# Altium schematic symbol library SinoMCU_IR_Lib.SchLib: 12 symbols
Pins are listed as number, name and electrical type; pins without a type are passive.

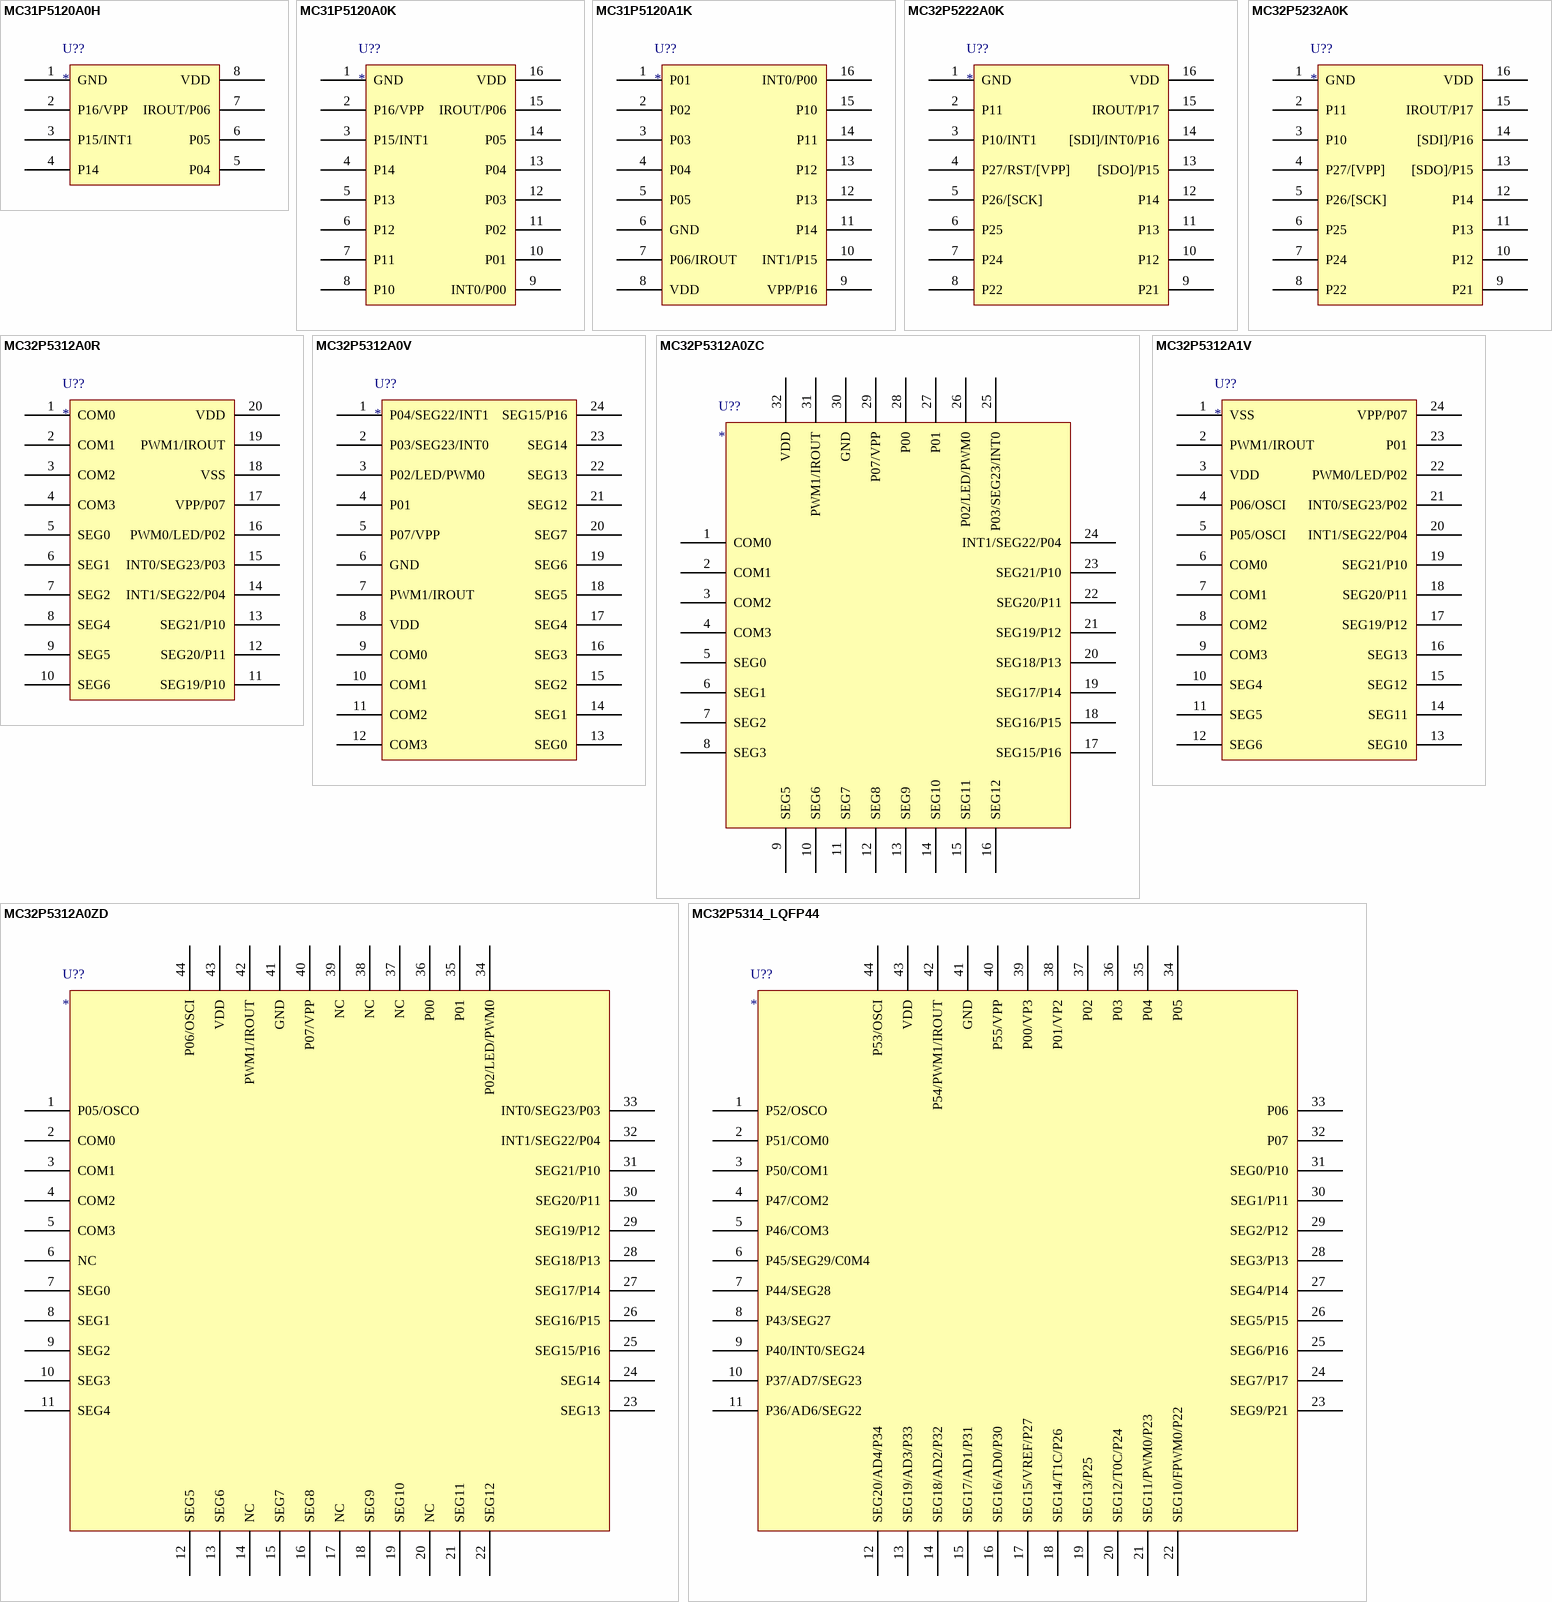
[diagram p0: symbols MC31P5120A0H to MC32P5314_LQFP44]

## MC31P5120A0H
designator U??
pins: 1 GND, 2 P16/VPP, 3 P15/INT1, 4 P14, 5 P04, 6 P05, 7 IROUT/P06, 8 VDD

## MC31P5120A0K
designator U??
pins: 1 GND, 2 P16/VPP, 3 P15/INT1, 4 P14, 5 P13, 6 P12, 7 P11, 8 P10, 9 INT0/P00, 10 P01, 11 P02, 12 P03, 13 P04, 14 P05, 15 IROUT/P06, 16 VDD

## MC31P5120A1K
designator U??
pins: 1 P01, 2 P02, 3 P03, 4 P04, 5 P05, 6 GND, 7 P06/IROUT, 8 VDD, 9 VPP/P16, 10 INT1/P15, 11 P14, 12 P13, 13 P12, 14 P11, 15 P10, 16 INT0/P00

## MC32P5222A0K
designator U??
pins: 1 GND, 2 P11, 3 P10/INT1, 4 P27/RST/[VPP], 5 P26/[SCK], 6 P25, 7 P24, 8 P22, 9 P21, 10 P12, 11 P13, 12 P14, 13 [SDO]/P15, 14 [SDI]/INT0/P16, 15 IROUT/P17, 16 VDD

## MC32P5232A0K
designator U??
pins: 1 GND, 2 P11, 3 P10, 4 P27/[VPP], 5 P26/[SCK], 6 P25, 7 P24, 8 P22, 9 P21, 10 P12, 11 P13, 12 P14, 13 [SDO]/P15, 14 [SDI]/P16, 15 IROUT/P17, 16 VDD

## MC32P5312A0R
designator U??
pins: 1 COM0, 2 COM1, 3 COM2, 4 COM3, 5 SEG0, 6 SEG1, 7 SEG2, 8 SEG4, 9 SEG5, 10 SEG6, 11 SEG19/P10, 12 SEG20/P11, 13 SEG21/P10, 14 INT1/SEG22/P04, 15 INT0/SEG23/P03, 16 PWM0/LED/P02, 17 VPP/P07, 18 VSS, 19 PWM1/IROUT, 20 VDD

## MC32P5312A0V
designator U??
pins: 1 P04/SEG22/INT1, 2 P03/SEG23/INT0, 3 P02/LED/PWM0, 4 P01, 5 P07/VPP, 6 GND, 7 PWM1/IROUT, 8 VDD, 9 COM0, 10 COM1, 11 COM2, 12 COM3, 13 SEG0, 14 SEG1, 15 SEG2, 16 SEG3, 17 SEG4, 18 SEG5, 19 SEG6, 20 SEG7, 21 SEG12, 22 SEG13, 23 SEG14, 24 SEG15/P16

## MC32P5312A0ZC
designator U??
pins: 1 COM0, 2 COM1, 3 COM2, 4 COM3, 5 SEG0, 6 SEG1, 7 SEG2, 8 SEG3, 9 SEG5, 10 SEG6, 11 SEG7, 12 SEG8, 13 SEG9, 14 SEG10, 15 SEG11, 16 SEG12, 17 SEG15/P16, 18 SEG16/P15, 19 SEG17/P14, 20 SEG18/P13, 21 SEG19/P12, 22 SEG20/P11, 23 SEG21/P10, 24 INT1/SEG22/P04, 25 P03/SEG23/INT0, 26 P02/LED/PWM0, 27 P01, 28 P00, 29 P07/VPP, 30 GND, 31 PWM1/IROUT, 32 VDD

## MC32P5312A0ZD
designator U??
pins: 1 P05/OSCO, 2 COM0, 3 COM1, 4 COM2, 5 COM3, 6 NC, 7 SEG0, 8 SEG1, 9 SEG2, 10 SEG3, 11 SEG4, 12 SEG5, 13 SEG6, 14 NC, 15 SEG7, 16 SEG8, 17 NC, 18 SEG9, 19 SEG10, 20 NC, 21 SEG11, 22 SEG12, 23 SEG13, 24 SEG14, 25 SEG15/P16, 26 SEG16/P15, 27 SEG17/P14, 28 SEG18/P13, 29 SEG19/P12, 30 SEG20/P11, 31 SEG21/P10, 32 INT1/SEG22/P04, 33 INT0/SEG23/P03, 34 P02/LED/PWM0, 35 P01, 36 P00, 37 NC, 38 NC, 39 NC, 40 P07/VPP, 41 GND, 42 PWM1/IROUT, 43 VDD, 44 P06/OSCI

## MC32P5312A1V
designator U??
pins: 1 VSS, 2 PWM1/IROUT, 3 VDD, 4 P06/OSCI, 5 P05/OSCI, 6 COM0, 7 COM1, 8 COM2, 9 COM3, 10 SEG4, 11 SEG5, 12 SEG6, 13 SEG10, 14 SEG11, 15 SEG12, 16 SEG13, 17 SEG19/P12, 18 SEG20/P11, 19 SEG21/P10, 20 INT1/SEG22/P04, 21 INT0/SEG23/P02, 22 PWM0/LED/P02, 23 P01, 24 VPP/P07

## MC32P5314_LQFP44
designator U??
pins: 1 P52/OSCO, 2 P51/COM0, 3 P50/COM1, 4 P47/COM2, 5 P46/COM3, 6 P45/SEG29/C0M4, 7 P44/SEG28, 8 P43/SEG27, 9 P40/INT0/SEG24, 10 P37/AD7/SEG23, 11 P36/AD6/SEG22, 12 SEG20/AD4/P34, 13 SEG19/AD3/P33, 14 SEG18/AD2/P32, 15 SEG17/AD1/P31, 16 SEG16/AD0/P30, 17 SEG15/VREF/P27, 18 SEG14/T1C/P26, 19 SEG13/P25, 20 SEG12/T0C/P24, 21 SEG11/PWM0/P23, 22 SEG10/FPWM0/P22, 23 SEG9/P21, 24 SEG7/P17, 25 SEG6/P16, 26 SEG5/P15, 27 SEG4/P14, 28 SEG3/P13, 29 SEG2/P12, 30 SEG1/P11, 31 SEG0/P10, 32 P07, 33 P06, 34 P05, 35 P04, 36 P03, 37 P02, 38 P01/VP2, 39 P00/VP3, 40 P55/VPP, 41 GND, 42 P54/PWM1/IROUT, 43 VDD, 44 P53/OSCI

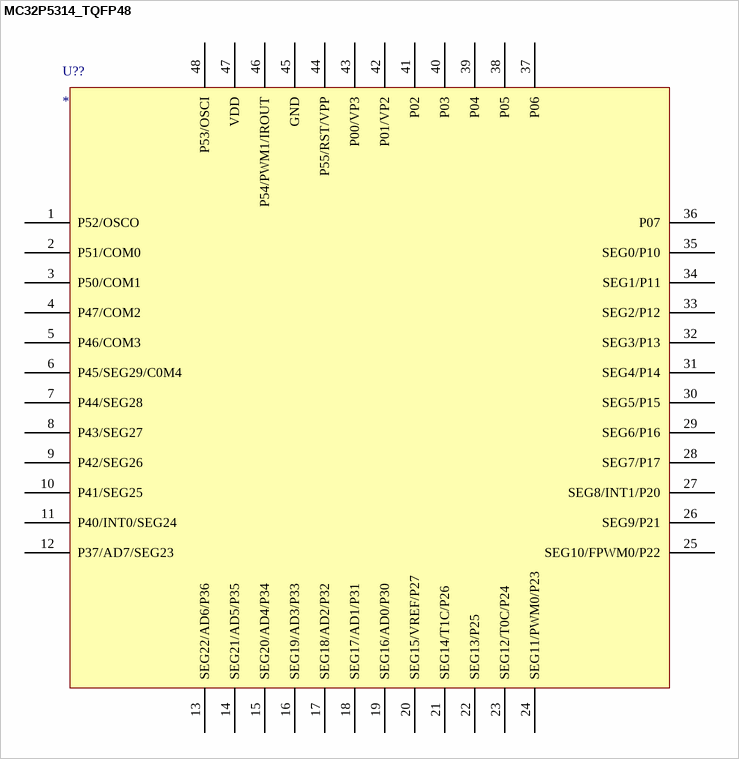
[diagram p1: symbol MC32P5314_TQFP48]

## MC32P5314_TQFP48
designator U??
pins: 1 P52/OSCO, 2 P51/COM0, 3 P50/COM1, 4 P47/COM2, 5 P46/COM3, 6 P45/SEG29/C0M4, 7 P44/SEG28, 8 P43/SEG27, 9 P42/SEG26, 10 P41/SEG25, 11 P40/INT0/SEG24, 12 P37/AD7/SEG23, 13 SEG22/AD6/P36, 14 SEG21/AD5/P35, 15 SEG20/AD4/P34, 16 SEG19/AD3/P33, 17 SEG18/AD2/P32, 18 SEG17/AD1/P31, 19 SEG16/AD0/P30, 20 SEG15/VREF/P27, 21 SEG14/T1C/P26, 22 SEG13/P25, 23 SEG12/T0C/P24, 24 SEG11/PWM0/P23, 25 SEG10/FPWM0/P22, 26 SEG9/P21, 27 SEG8/INT1/P20, 28 SEG7/P17, 29 SEG6/P16, 30 SEG5/P15, 31 SEG4/P14, 32 SEG3/P13, 33 SEG2/P12, 34 SEG1/P11, 35 SEG0/P10, 36 P07, 37 P06, 38 P05, 39 P04, 40 P03, 41 P02, 42 P01/VP2, 43 P00/VP3, 44 P55/RST/VPP, 45 GND, 46 P54/PWM1/IROUT, 47 VDD, 48 P53/OSCI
